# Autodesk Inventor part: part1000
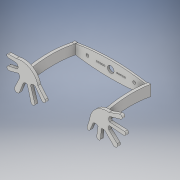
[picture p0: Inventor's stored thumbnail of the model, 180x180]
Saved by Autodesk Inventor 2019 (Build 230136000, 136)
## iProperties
Created: 2020-02
Part Number: part1000
Material: Generic
Document SubType Name: Modeling
Designer: shivu
Density: 1 g/cm^3
Appearance: Default
Author: shivu
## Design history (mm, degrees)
sketch "Sketch1"
  geometry: L1 (16.371, 11.867)-(16.371, 1.603); L2 (-59.091, 1.603)-(-59.091, 11.867); C1 r 3.5 at (-21.431, 7.007); C2 r 0.75 at (-28.303, 7.007); C3 r 0.75 at (-32.16, 7.007); C4 r 0.75 at (-30.328, 7.007); C5 r 0.75 at (-34.28, 7.007); C6 r 0.75 at (-36.348, 7.007); C7 r 0.75 at (-6.514, 7.007); C8 r 0.75 at (-8.582, 7.007); C9 r 0.75 at (-10.702, 7.007); C10 r 0.75 at (-12.534, 7.007); C11 r 0.75 at (-14.559, 7.007); C12 r 1.5 at (-46.431, 7.408); C13 r 1.5 at (3.569, 7.408); A1 r 203.362 centre (-21.36, -187.965) between (16.371, 11.867) and (-59.091, 11.867); A2 r 235.808 centre (-21.36, 234.373) between (-59.091, 1.603) and (16.371, 1.603); 1 further point
  constraints: 15 centre point, 4 end point, 4 point on circle, 1 parallel
  dimensions: "d43" = 7 diameter of C1
extrude "Extrusion12" join sketch "Sketch1" distance "d59" = 3; taper "d60" = 0 deg
extrude "Extrusion18" join sketch "Sketch1" distance "d79" = 2; taper "d80" = 0 deg
sketch "Sketch16"
  geometry: L1 (0, 5.485)-(47.994, 6.239); L2 (0, 10.264)-(3, 10.264); L3 (0, 10.264)-(3, 10.264); L4 (0, 10.264)-(0, 0); L5 (0, 10.264)-(0, 0); L6 (0, 0)-(3, 0); L7 (0, 0)-(3, 0); L8 (47.913, 11.385)-(47.913, 0); A1 r 112.309 centre (28.201, -99.181) between (47.913, 11.385) and (3, 10.264); A2 r 118.118 centre (25.457, -115.964) between (47.913, 0) and (3, 0); 1 further point
  constraints: 16 end point, 4 point on circle, 2 centre point, 2 collinear, 2 vertical
extrude "Extrusion19" join sketch "Sketch16" taper "d82" = 0 deg; distance "d83" = 3
sketch "Sketch17"
  geometry: L1 (0, 5.485)-(47.994, 6.239); L2 (0, 10.264)-(3, 10.264); L3 (0, 10.264)-(3, 10.264); L4 (0, 10.264)-(0, 0); L5 (0, 10.264)-(0, 0); L6 (0, 0)-(3, 0); L7 (0, 0)-(3, 0); L8 (47.913, 11.385)-(47.913, 0); A1 r 112.309 centre (28.201, -99.181) between (47.913, 11.385) and (3, 10.264); A2 r 118.118 centre (25.457, -115.964) between (47.913, 0) and (3, 0); 1 further point
  constraints: 16 end point, 4 point on circle, 2 centre point, 2 collinear, 2 vertical
extrude "Extrusion20" join sketch "Sketch17" taper "d85" = 0 deg; distance "d86" = 3
sketch "Sketch18"
  geometry: L1 (0, 5.913)-(60.134, 5.913); L2 (0.904, 0)-(-3, 0); L3 (-1.5, 2.957)-(28.5, 2.957); L4 (8.24, 4.55)-(24.432, 5.206); L5 (8.24, 1.001)-(24.602, 1.001); L6 (8.24, -3.379)-(17.87, -10.644); L7 (4.835, -6.783)-(14.567, -15.021); L8 (0.456, -6.783)-(0.456, -16.838); L9 (-3.095, -6.783)-(-3.618, -16.768); L10 (8.24, 9.804)-(19.279, 14.016); L11 (7.019, 13.002)-(17.75, 17.972); L12 (-8.348, -6.783)-(-10.991, -15.027); L13 (-12.156, -5.563)-(-14.174, -14); C1 r 0.75 at (25.626, 3); A1 r 3.436 centre (10.456, 7.177) between (8.24, 9.804) and (8.24, 4.55); A2 r 3.382 centre (10.817, -1.189) between (8.24, 1.001) and (8.24, -3.379); A3 r 3.436 centre (-5.722, -8.999) between (-3.095, -6.783) and (-8.348, -6.783); A4 r 3.382 centre (2.645, -9.36) between (4.835, -6.783) and (0.456, -6.783); A5 r 2.551 centre (23.075, 3.045) between (24.602, 1.001) and (24.432, 5.206); A6 r 2.908 centre (15.445, -12.249) between (14.567, -15.021) and (17.87, -10.644); A7 r 2.038 centre (-1.582, -16.838) between (-3.618, -16.768) and (0.456, -16.838); A8 r 2.125 centre (18.643, 16.044) between (19.279, 14.016) and (17.75, 17.972); A9 r 1.672 centre (-12.583, -14.517) between (-14.174, -14) and (-10.991, -15.027); A10 r 18.321 centre (6.163, -5.299) between (7.019, 13.002) and (-12.156, -5.563); 1 further point
  constraints: 26 end point, 21 point on circle, 11 centre point, 3 tangent, 2 horizontal, 1 vertical
extrude "Extrusion21" join sketch "Sketch18" taper "d88" = 0 deg; distance "d89" = 3
sketch "Sketch19"
  geometry: L1 (0, 5.913)-(60.134, 5.913); L2 (0.904, 0)-(-3, 0); L3 (-1.5, 2.957)-(28.5, 2.957); L4 (8.24, 4.55)-(24.432, 5.206); L5 (8.24, 1.001)-(24.602, 1.001); L6 (8.24, -3.379)-(17.87, -10.644); L7 (4.835, -6.783)-(14.567, -15.021); L8 (0.456, -6.783)-(0.456, -16.838); L9 (-3.095, -6.783)-(-3.618, -16.768); L10 (8.24, 9.804)-(19.279, 14.016); L11 (7.019, 13.002)-(17.75, 17.972); L12 (-8.348, -6.783)-(-10.991, -15.027); L13 (-12.156, -5.563)-(-14.174, -14); C1 r 0.75 at (25.626, 3); A1 r 3.436 centre (10.456, 7.177) between (8.24, 9.804) and (8.24, 4.55); A2 r 3.382 centre (10.817, -1.189) between (8.24, 1.001) and (8.24, -3.379); A3 r 3.436 centre (-5.722, -8.999) between (-3.095, -6.783) and (-8.348, -6.783); A4 r 3.382 centre (2.645, -9.36) between (4.835, -6.783) and (0.456, -6.783); A5 r 2.551 centre (23.075, 3.045) between (24.602, 1.001) and (24.432, 5.206); A6 r 2.908 centre (15.445, -12.249) between (14.567, -15.021) and (17.87, -10.644); A7 r 2.038 centre (-1.582, -16.838) between (-3.618, -16.768) and (0.456, -16.838); A8 r 2.125 centre (18.643, 16.044) between (19.279, 14.016) and (17.75, 17.972); A9 r 1.672 centre (-12.583, -14.517) between (-14.174, -14) and (-10.991, -15.027); A10 r 18.321 centre (6.163, -5.299) between (7.019, 13.002) and (-12.156, -5.563); 1 further point
  constraints: 26 end point, 21 point on circle, 11 centre point, 3 tangent, 2 horizontal, 1 vertical
extrude "Extrusion22" join sketch "Sketch19" taper "d91" = 0 deg; distance "d92" = 3
body "Solid1"
